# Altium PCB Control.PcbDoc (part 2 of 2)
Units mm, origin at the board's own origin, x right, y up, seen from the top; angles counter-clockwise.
Board outline 30.5 x 82 mm, 2 copper layers (Top Layer, Bottom Layer), stack 1.071 mm thick; 79 components, 65 nets, 365 pads, 467 vias.
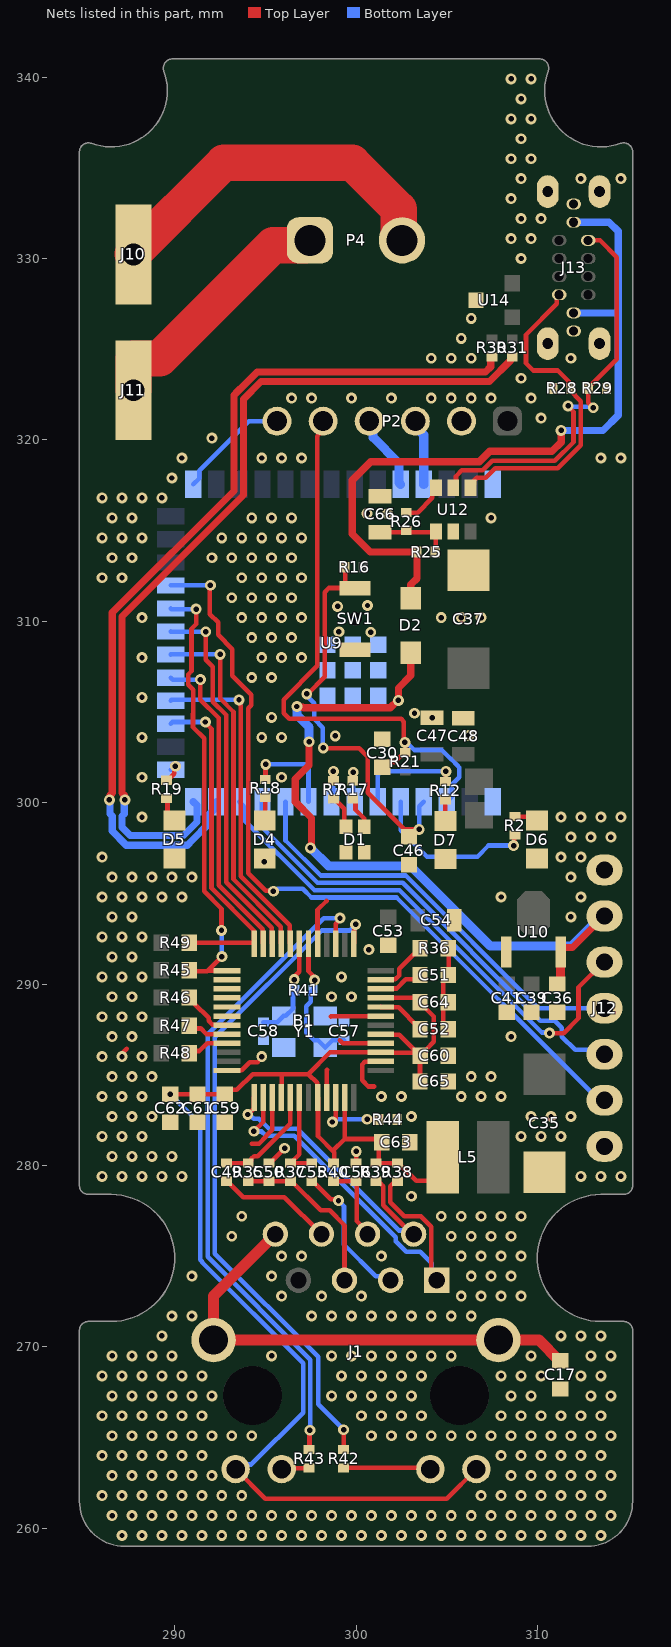
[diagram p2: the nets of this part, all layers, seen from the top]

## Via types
v1: diameter 0.6, hole 0.3, Top Layer to Bottom Layer, tented both sides, 467 vias

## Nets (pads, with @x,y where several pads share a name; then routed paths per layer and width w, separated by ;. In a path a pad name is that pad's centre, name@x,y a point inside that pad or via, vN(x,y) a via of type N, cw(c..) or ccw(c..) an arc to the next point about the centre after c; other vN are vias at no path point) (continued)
G: B1.3 B1.9 B1.14 B1.16 B1.19 B1.29 B1.38 B1.39 B1.40 B1.41 B1.42 B1.48 C17.1 C30.1 C35.2 C36.1 C37.2 C39.1 C41.1 C46.1 C47.1 C48.1 C50.1 C51.2 C52.2 C53.1 C54.1 C56.1 C57.1 C58.1 C59.1 C60.1 C61.1 C62.1 C63.1 C64.1 C65.1 C66.1 D1.3 D1.4 D4.2 D5.2 D6.2 D7.2 J12.1 J12.7 J13.A1/B12 J13.A12/B1 J13.MNT1 J13.MNT2 J13.MNT3 J13.MNT4 P2.2 R28.2 R29.2 R36.2 R44.1 SW1.2 U9.1 U9.40 U9.41 U9.42 U9.43 U9.44 U9.45 U9.46 U9.47 U9.48 U9.49 U10.1 U12.2 U14.3 Y1.2 Y1.4 | length 24.6
  Top Layer w0.254: v1@287.02,286.106 287.35,286.436 ; B1.48@292.738,285.235 292.761,285.258 293.693,285.258 294.134,285.699 294.589,285.699 ; 294.257,281.204 294.649,281.204 295.048,281.603 295.048,281.637 295.377,281.965 B1.3@295.377,283.745 ; C50.1@295.199,280.129 295.249,280.129 296.062,280.942 v1(296.062,280.949) ; B1.29@297.879,292.223 297.879,294.086 298.374,294.581 ; B1.9@298.379,283.747 298.379,285.247 298.399,285.267 ; 298.602,288.214 298.624,288.235 B1.19@301.367,288.235 ; 299.11,286.893 299.268,286.735 B1.16@301.367,286.735 ; C56.1@299.999,280.129 300.006,280.135 300.006,280.77 v1(300.012,280.776) ; 300.99,284.353 300.685,284.353 300.34,284.698 300.34,285.563 300.489,285.712 301.344,285.712 B1.14@301.367,285.735 ; C52.2@304.838,287.452 304.991,287.604 304.82,287.775 304.82,288.729 305.092,289.001 304.82,289.274 304.82,290.227 305.118,290.525 305.118,291.65 305.074,291.694 305.067,291.694 305.067,291.948 R36.2@305.092,291.973
  other v1: 287.1,259.6 288.2,259.6 289.3,259.6 290.4,259.6 291.5,259.6 292.6,259.6 293.7,259.6 294.8,259.6 295.9,259.6 297,259.6 298.1,259.6 299.2,259.6 300.3,259.6 301.4,259.6 302.5,259.6 303.6,259.6 304.7,259.6 305.8,259.6 306.9,259.6 308,259.6 309.1,259.6 310.2,259.6 311.3,259.6 312.4,259.6 313.5,259.6 286.55,260.7 287.65,260.7 288.75,260.7 289.85,260.7 290.95,260.7 292.05,260.7 293.15,260.7 294.25,260.7 295.35,260.7 296.45,260.7 297.55,260.7 298.65,260.7 299.75,260.7 300.85,260.7 301.95,260.7 303.05,260.7 304.15,260.7 305.25,260.7 306.35,260.7 307.45,260.7 308.55,260.7 309.65,260.7 310.75,260.7 311.85,260.7 312.95,260.7 314.05,260.7 286,261.8 287.1,261.8 288.2,261.8 289.3,261.8 290.4,261.8 291.5,261.8 292.6,261.8 293.7,261.8 306.9,261.8 308,261.8 309.1,261.8 310.2,261.8 311.3,261.8 312.4,261.8 313.5,261.8 286.55,262.9 287.65,262.9 288.75,262.9 289.85,262.9 290.95,262.9 292.05,262.9 308.55,262.9 309.65,262.9 310.75,262.9 311.85,262.9 312.95,262.9 314.05,262.9 286,264 287.1,264 288.2,264 289.3,264 290.4,264 291.5,264 308,264 309.1,264 310.2,264 311.3,264 312.4,264 313.5,264 286.55,265.1 287.65,265.1 288.75,265.1 289.85,265.1 290.95,265.1 292.05,265.1 293.15,265.1 294.25,265.1 300.85,265.1 301.95,265.1 303.05,265.1 304.15,265.1 305.25,265.1 306.35,265.1 307.45,265.1 308.55,265.1 309.65,265.1 310.75,265.1 311.85,265.1 312.95,265.1 314.05,265.1 286,266.2 287.1,266.2 288.2,266.2 289.3,266.2 290.4,266.2 291.5,266.2 300.3,266.2 301.4,266.2 302.5,266.2 303.6,266.2 308,266.2 309.1,266.2 310.2,266.2 311.3,266.2 312.4,266.2 313.5,266.2 286.55,267.3 287.65,267.3 288.75,267.3 289.85,267.3 290.95,267.3 292.05,267.3 298.65,267.3 299.75,267.3 300.85,267.3 301.95,267.3 303.05,267.3 308.55,267.3 309.65,267.3 312.95,267.3 314.05,267.3 286,268.4 287.1,268.4 288.2,268.4 289.3,268.4 290.4,268.4 291.5,268.4 299.2,268.4 300.3,268.4 301.4,268.4 302.5,268.4 303.6,268.4 308,268.4 309.1,268.4 310.2,268.4 312.4,268.4 313.5,268.4 286.55,269.5 287.65,269.5 288.75,269.5 289.85,269.5 295.35,269.5 298.65,269.5 299.75,269.5 300.85,269.5 301.95,269.5 303.05,269.5 304.15,269.5 305.25,269.5 309.65,269.5 312.95,269.5 314.05,269.5 289.3,270.6 311.3,270.6 312.4,270.6 313.5,270.6 289.85,271.7 290.95,271.7 297.55,271.7 298.65,271.7 299.75,271.7 300.85,271.7 301.95,271.7 303.05,271.7 304.15,271.7 305.25,271.7 306.35,271.7 295.9,272.8 298.1,272.8 300.3,272.8 305.8,272.8 306.9,272.8 308,272.8 309.1,272.8 290.95,273.9 295.35,273.9 306.35,273.9 307.45,273.9 308.55,273.9 295.9,275 297,275 301.4,275 305.8,275 306.9,275 308,275 309.1,275 293.15,276.1 305.25,276.1 306.35,276.1 307.45,276.1 308.55,276.1 293.7,277.2 304.7,277.2 305.8,277.2 306.9,277.2 308,277.2 309.1,277.2 303.05,278.3 286,279.4 287.1,279.4 288.2,279.4 289.3,279.4 290.4,279.4 312.4,279.4 313.5,279.4 314.6,279.4 286.55,280.5 287.65,280.5 288.75,280.5 289.85,280.5 286,281.6 287.1,281.6 288.2,281.6 309.1,281.6 310.2,281.6 311.3,281.6 286.55,282.7 287.65,282.7 288.75,282.7 303.05,282.7 309.65,282.7 310.75,282.7 311.85,282.7 286,283.8 287.1,283.8 288.2,283.8 301.4,283.8 302.5,283.8 305.8,283.8 306.9,283.8 308,283.8 286.55,284.9 287.65,284.9 288.75,284.9 306.35,284.9 307.45,284.9 286,286 287.1,286 288.2,286 294.8,286 286.55,287.1 287.65,287.1 308.55,287.1 286,288.2 287.1,288.2 288.2,288.2 286.55,289.3 287.65,289.3 298.65,289.3 299.75,289.3 286,290.4 287.1,290.4 288.2,290.4 299.2,290.4 286.55,291.5 287.65,291.5 300.711,291.897 286,292.6 287.1,292.6 288.2,292.6 286.55,293.7 287.65,293.7 311.85,293.7 286,294.8 287.1,294.8 288.2,294.8 289.3,294.8 290.4,294.8 308,294.8 312.4,294.8 286.55,295.9 287.65,295.9 288.75,295.9 289.85,295.9 290.95,295.9 311.85,295.9 294.945,296.748 286,297 311.3,297 312.4,297 311.85,298.1 312.95,298.1 314.05,298.1 288.2,299.2 311.3,299.2 312.4,299.2 313.5,299.2 314.6,299.2 288.2,301.4 295.9,301.4 288.2,303.6 294.8,303.6 295.9,303.6 298.856,303.682 306.222,303.708 304.191,304.682 295.35,304.7 303.225,304.927 288.2,305.8 294.25,306.9 295.35,306.9 288.2,308 294.8,308 295.9,308 297,308 294.25,309.1 295.35,309.1 296.45,309.1 300.812,309.397 299.06,309.423 288.2,310.2 293.7,310.2 294.8,310.2 295.9,310.2 297,310.2 304.7,310.2 305.8,310.2 306.9,310.2 298.983,310.82 300.634,310.871 293.15,311.3 294.25,311.3 295.35,311.3 296.45,311.3 286,312.4 287.1,312.4 293.7,312.4 294.8,312.4 295.9,312.4 297,312.4 286.55,313.5 287.65,313.5 292.05,313.5 293.15,313.5 294.25,313.5 295.35,313.5 296.45,313.5 286,314.6 287.1,314.6 288.2,314.6 292.6,314.6 293.7,314.6 294.8,314.6 295.9,314.6 297,314.6 286.55,315.7 287.65,315.7 294.25,315.7 295.35,315.7 296.45,315.7 307.45,315.7 301.727,315.925 300.609,315.951 286,316.8 287.1,316.8 288.2,316.8 289.3,316.8 289.85,317.9 290.4,319 294.8,319 295.9,319 297,319 313.5,319 314.6,319 292.05,320.1 310.2,321.2 296.45,322.3 297.55,322.3 299.75,322.3 301.95,322.3 304.15,322.3 305.25,322.3 306.35,322.3 307.45,322.3 309.65,322.3 309.1,323.4 304.15,324.5 305.25,324.5 306.35,324.5 311.85,324.5 305.8,325.6 306.35,326.7 309.1,330 308.55,331.1 309.65,331.1 309.1,332.2 310.2,332.2 308.55,333.3 309.1,334.4 312.4,334.4 314.6,334.4 308.55,335.5 309.65,335.5 309.1,336.6 308.55,337.7 309.65,337.7 309.1,338.8 308.55,339.9 309.65,339.9
GND_PE: C17.2 J1.8 J1.13 J1.14 | length 26.8
  Top Layer w0.6: J1.8@295.555,276.215 292.15,272.81 J1.14@292.15,270.375 J1.13@307.85,270.375 310.079,270.375 311.227,269.228 C17.2@311.252,269.228
NetB1_4: B1.4 B1.8 B1.11 B1.15 B1.17 B1.21 C59.2 C60.2 C61.2 C62.2 C63.2 C64.2 C65.2 J1.9 J1.12 L5.2 R38.2 R39.2 R40.1 | length 83
  Top Layer w0.254: v1(289.763,283.934) C61.2@291.262,283.934 C59.2@292.76,283.934 292.991,284.165 293.436,284.165 294.31,285.039 295.899,285.039 ; J1.12@293.36,263.265 295.006,261.619 304.994,261.619 J1.9@306.64,263.265 ; B1.4@295.879,283.747 295.902,283.77 295.902,284.478 295.904,284.48 295.904,285.033 295.899,285.039 ; 298.724,280.802 299.379,281.457 ; R40.1@298.755,280.129 298.811,280.184 298.811,280.716 297.902,281.624 297.902,283.724 297.856,283.77 297.856,284.549 297.367,285.039 ; B1.11@299.379,283.747 299.379,281.457 ; B1.17@301.367,287.235 301.39,287.212 302.385,287.212 303.219,286.378 303.244,286.378 303.307,286.315 303.307,286.29 C60.2@303.542,286.055 ; B1.21@301.367,289.235 301.387,289.255 303.274,289.255 C64.2@303.528,289.001 303.528,288.976 304.292,288.212 304.292,286.811 303.858,286.378 303.84,286.378 303.542,286.08 C60.2@303.542,286.062 ; C60.2@303.23,286.212 301.39,286.212 B1.15@301.367,286.235 298.563,286.235 297.367,285.039 ; C65.2@303.528,284.632 C60.2@303.528,286.04 ; L5.2@304.775,280.441 304.775,279.922 304.002,279.149 303.315,279.149 302.335,280.129 R38.2@302.285,280.129 R39.2@301.092,280.129 301.121,280.129 301.244,280.252 301.244,281.115 C63.2@301.409,281.28 301.231,281.457 299.379,281.457 ; 295.899,285.039 297.367,285.039
  Bottom Layer w0.254: v1(289.763,283.934) 291.412,282.286 291.412,274.792 291.516,274.688 291.516,274.65 297.081,269.085 297.081,266.372 294.225,263.517 293.612,263.517 J1.12@293.36,263.265
NetB1_10: B1.10 R44.2 | length 4.1
  Top Layer w0.254: v1(298.698,282.397) 298.755,282.454 298.755,282.473 298.879,282.598 B1.10@298.879,283.747 ; v1(300.609,282.55) 300.622,282.537 301.239,282.537 R44.2@301.252,282.524
  Bottom Layer w0.254: v1(298.698,282.397) 298.792,282.397 298.944,282.55 v1(300.609,282.55)
NetB1_20: B1.20 C52.1 | length 2.6
  Top Layer w0.254: B1.20@301.367,288.735 301.39,288.712 302.358,288.712 303.441,287.629 C52.1@303.441,287.604
NetB1_22: B1.22 C51.1 | length 2.5
  Top Layer w0.254: B1.22@301.367,289.735 301.39,289.758 302.241,289.758 302.747,290.264 303.307,290.264 C51.1@303.542,290.5
NetB1_23: B1.23 R36.1 | length 3.1
  Top Layer w0.254: B1.23@301.367,290.235 301.39,290.258 302.169,290.258 302.382,290.47 302.382,290.85 303.182,291.65 303.23,291.65 303.528,291.948 R36.1@303.528,291.971
NetB1_25: B1.25 R42.2 | length 37.1
  Top Layer w0.254: R42.2@299.314,264.33 v1(299.314,265.43) ; B1.25@299.879,292.223 299.902,292.246 299.902,293.117 299.978,293.192 v1(299.978,293.286)
  Bottom Layer w0.254: v1(299.314,265.43) 297.917,266.827 297.917,269.443 292.22,275.14 292.22,287.062 298.11,292.952 299.644,292.952 v1(299.978,293.286)
NetB1_27: B1.27 R43.2 | length 36.7
  Top Layer w0.254: R43.2@297.409,264.33 297.434,264.355 297.434,265.379 v1(297.459,265.405) ; B1.27@298.879,292.223 298.879,293.325 299.118,293.563 v1(299.118,293.633)
  Bottom Layer w0.254: v1(297.459,265.405) 297.485,265.43 297.485,269.291 291.816,274.96 291.816,287.229 298.22,293.633 v1(299.118,293.633)
NetB1_30: B1.30 C57.2 R41.2 Y1.1 | length 7.8
  Top Layer w0.254: B1.30@297.379,292.223 297.379,290.702 297.713,290.368 v1(297.713,290.22)
  Bottom Layer w0.254: v1(297.713,290.22) 297.671,290.178 297.671,289.704 297.506,289.539 297.506,289.019 297.256,288.769 297.256,287.325 297.682,286.899 297.907,286.899 Y1.1@298.305,286.501 298.703,286.899 299.337,286.899 C57.2@299.339,286.901
NetB1_31: B1.31 C58.2 R41.1 Y1.3 | length 7.1
  Top Layer w0.254: v1(296.596,290.246) 296.596,290.394 296.879,290.677 B1.31@296.879,292.223
  Bottom Layer w0.254: C58.2@294.894,287.901 295.656,287.901 295.664,287.893 296.021,288.251 Y1.3@296.13,288.251 ; R41.1@296.596,289.662 v1(296.596,290.246) ; R41.1@296.629,289.662 296.528,289.56 Y1.3@296.528,288.649 ; Y1.3@296.13,288.251 Y1.3@296.005,288.251 Y1.3@296.13,288.251 ; Y1.3@296.13,288.251 Y1.3@296.528,288.649 ; Y1.3@296.13,288.251 Y1.3@296.528,288.649 ; Y1.3@296.13,288.251 Y1.3@296.528,288.649
NetB1_32: B1.32 U9.18 | length 18.4
  Top Layer w0.254: v1(293.548,305.664) 293.614,305.597 293.614,305.38 293.652,305.342 293.652,295.944 296.356,293.239 296.356,292.246 B1.32@296.379,292.223
  Bottom Layer w0.254: U9.18@289.783,305.625 289.822,305.664 v1(293.548,305.664)
NetB1_33: B1.33 U9.20 | length 20.1
  Top Layer w0.254: v1(292.506,308.178) 292.506,305.742 293.248,305.001 293.248,295.777 295.856,293.168 295.856,292.246 B1.33@295.879,292.223
  Bottom Layer w0.254: U9.20@289.783,308.165 289.796,308.178 v1(292.506,308.178)
NetB1_34: B1.34 U9.21 | length 20.7
  Top Layer w0.254: v1(291.719,309.423) 291.719,307.873 292.102,307.49 292.102,305.575 292.844,304.833 292.844,295.609 295.356,293.097 295.356,292.246 B1.34@295.379,292.223
  Bottom Layer w0.254: U9.21@289.783,309.435 289.796,309.423 v1(291.719,309.423)
NetB1_35: B1.35 U9.19 | length 17.7
  Top Layer w0.254: v1(291.421,306.786) 291.421,305.684 292.44,304.666 292.44,295.442 294.856,293.025 294.856,292.246 B1.35@294.879,292.223
  Bottom Layer w0.254: U9.19@289.783,306.895 289.892,306.786 v1(291.421,306.786)
NetB1_36: B1.36 R49.2 U9.17 | length 18.8
  Top Layer w0.254: R49.2@290.818,292.278 B1.36@294.356,292.278 ; v1(291.695,304.448) 291.695,304.403 292.036,304.062 292.036,295.274 294.356,292.954 B1.36@294.356,292.278 ; B1.36@294.379,292.223 294.379,292.255 B1.36@294.356,292.278
  Bottom Layer w0.254: U9.17@289.783,304.355 289.876,304.448 v1(291.695,304.448)
NetB1_37: B1.37 R45.2 U9.22 | length 24.8
  Top Layer w0.254: R45.2@290.818,290.754 290.868,290.703 291.795,290.703 v1(292.608,291.516) ; v1(291.186,310.667) 291.186,309.852 290.932,309.598 290.932,307.259 290.74,307.068 290.74,306.504 291.017,306.227 291.017,304.9 291.014,304.896 291.014,304.166 291.632,303.548 291.632,295.107 292.583,294.156 v1(292.583,292.964) ; 291.795,290.735 B1.37@292.891,290.735
  Bottom Layer w0.254: U9.22@289.783,310.705 289.821,310.667 v1(291.186,310.667) ; v1(292.583,292.964) 292.595,292.951 292.595,291.529 v1(292.608,291.516)
NetB1_43: B1.43 R46.2 | length 2.8
  Top Layer w0.254: R46.2@290.818,289.255 291.116,288.957 291.116,288.893 291.877,288.132 291.877,287.97 292.089,287.758 292.868,287.758 B1.43@292.891,287.735
NetB1_44: B1.44 R47.2 | length 2.3
  Top Layer w0.254: R47.2@290.818,287.706 290.97,287.553 291.44,287.553 291.758,287.235 B1.44@292.891,287.235
NetB1_45: B1.45 R48.2 | length 2.4
  Top Layer w0.254: R48.2@290.818,286.182 290.881,286.118 291.072,286.309 291.363,286.309 291.79,286.735 B1.45@292.891,286.735
NetC30_2: C30.2 P2.5 R21.1 U9.3 | length 32.9
  Top Layer w0.254: P2.5@298.19,321.031 297.932,320.773 297.932,320.273 297.868,320.209 297.868,307.539 296.012,305.682 296.012,304.924 296.314,304.622 302.489,304.622 302.641,304.47 302.641,303.378 v1(302.692,303.327) 302.704,303.314 302.704,302.773 R21.1@302.717,302.76 302.667,302.76 302.147,302.24 301.745,302.24 C30.2@301.447,301.942
  Bottom Layer w0.254: v1(302.692,303.327) 302.785,303.327 303.211,302.901 304.729,302.901 305.222,302.408 305.234,302.408 305.633,302.009 305.633,301.997 305.689,301.941 305.689,301.396 305.288,300.996 305.288,300.335 U9.3@305.003,300.05
NetC46_2: C46.2 R16.1 SW1.1 U9.4 | length 22.3
  Top Layer w0.254: v1(297.286,305.994) 297.33,305.994 298.272,306.936 298.272,311.607 298.499,311.834 SW1.1@299.259,311.834 ; v1(298.196,303.022) 298.217,303.001 300.17,303.001 300.655,302.517 300.655,300.538 302.666,298.526 v1(303.479,298.526) ; R16.1@299.398,312.979 299.398,311.973 SW1.1@299.259,311.834 ; SW1.1@299.949,311.834 SW1.1@299.259,311.834
  Bottom Layer w0.254: v1(297.286,305.994) 297.286,305.9 297.696,305.49 297.696,304.619 298.175,304.14 298.175,303.043 v1(298.196,303.022) ; v1(303.479,298.526) 303.479,299.796 U9.4@303.733,300.05
NetC50_2: C50.2 J1.5 R35.2 R37.1 | length 9.3
  Top Layer w0.254: R35.2@294.056,279.129 C50.2@295.199,279.129 296.22,279.129 296.443,279.129 298.051,277.52 298.552,277.52 299.365,276.707 J1.5@299.365,273.675
NetC56_2: C56.2 J1.4 R40.2 | length 4.5
  Top Layer w0.254: R40.2@298.755,279.129 300.049,279.129 300.049,276.937 300.635,276.351 J1.4@300.635,276.215
NetC66_2: C66.2 R25.2 R26.1 U12.1 | length 4.3
  Top Layer w0.254: C66.2@301.32,314.9 304.355,314.9 U12.1@304.409,314.954 304.388,314.934 304.388,313.837 R25.2@304.368,313.817
NetD1_1: D1.1 R7.1 | length 1.9
  Top Layer w0.254: R7.1@298.755,300.211 298.805,300.211 299.353,299.662 299.353,298.763 D1.1@299.449,298.667
NetD1_2: D1.2 R17.1 | length 1.8
  Top Layer w0.254: R17.1@299.822,300.211 299.851,300.211 299.974,300.088 299.974,299.601 300.449,299.126 D1.2@300.449,298.667
NetD4_1: D4.1 R18.1 | length 1.3
  Top Layer w0.254: D4.1@294.97,299.017 294.996,299.043 R18.1@294.996,300.287
NetD5_1: D5.1 R19.1 | length 1.4
  Top Layer w0.254: R19.1@289.56,300.236 289.607,300.189 289.607,299.402 D5.1@289.992,299.017
NetD6_1: D6.1 R2.1 | length 1.4
  Top Layer w0.254: R2.1@308.762,299.229 309.516,299.229 309.643,299.356 D6.1@309.982,299.017
NetD7_1: D7.1 R12.1 | length 1.2
  Top Layer w0.254: D7.1@304.927,298.992 R12.1@304.927,300.16
NetJ1_10: J1.10 R42.1 | length 4.8
  Top Layer w0.254: R42.1@299.314,263.33 304.035,263.33 J1.10@304.1,263.265
NetJ1_11: J1.11 R43.1 | length 1.5
  Top Layer w0.254: J1.11@295.9,263.265 295.932,263.297 297.376,263.297 R43.1@297.409,263.33
NetJ10_1: J10.1 P4.2 | length 19.6
  Top Layer w2: J10.1@287.68,330.251 292.71,335.28 299.796,335.28 302.358,332.718 302.358,331.182 P4.2@302.54,331
NetJ11_1: J11.1 P4.1 | length 14.2
  Top Layer w2: J11.1@287.731,322.733 287.731,324.483 289.177,324.483 295.419,330.725 297.185,330.725 P4.1@297.46,331
NetJ12_3: J12.3 U9.12 | length 28.4
  Top Layer w0.254: v1(310.667,287.299) 311.455,287.299 312.268,288.112 312.268,289.814 J12.3@313.665,291.211
  Bottom Layer w0.254: U9.12@293.573,300.05 293.819,299.804 293.819,299.068 297.711,295.176 302.399,295.176 310.244,287.331 310.636,287.331 v1(310.667,287.299)
NetJ12_4: J12.4 U9.10 | length 23.5
  Bottom Layer w0.254: U9.10@296.113,300.05 296.113,297.917 298.046,295.984 302.734,295.984 310.047,288.671 J12.4@313.665,288.671
NetJ12_5: J12.5 U9.11 | length 25.7
  Bottom Layer w0.254: U9.11@294.843,300.05 294.818,300.025 294.818,298.641 297.879,295.58 302.567,295.58 310.166,287.98 310.949,287.98 311.348,287.581 311.348,287.101 312.076,286.373 313.423,286.373 J12.5@313.665,286.131
NetJ12_6: J12.6 U9.23 | length 44
  Top Layer w0.254: v1(291.973,311.988) 291.946,311.961 291.946,310.397 292.4,309.943 292.4,309.248 293.187,308.46 293.187,307.724 293.187,306.987 293.83,306.345 294.229,305.946 294.229,305.382 294.056,305.209 294.056,296.111 295.021,295.146 295.413,295.146 v1(295.444,295.114)
  Bottom Layer w0.254: U9.23@289.796,311.988 v1(291.973,311.988) ; v1(295.444,295.114) 295.538,295.114 295.684,295.261 297.055,295.261 297.544,294.772 302.232,294.772 313.413,283.591 J12.6@313.665,283.591
NetJ13_A5: J13.A5 R28.1 U12.4 | length 18.3
  Top Layer w0.254: U12.4@306.309,317.354 306.507,317.552 306.507,317.771 306.656,317.92 307.16,317.92 307.68,318.44 311.125,318.44 312.395,319.71 312.395,322.14 311.777,322.758 R28.1@311.853,322.834 311.73,322.957 311.73,323.219 311.125,323.825 309.781,323.825 309.372,324.233 309.372,325.806 311.07,327.504 311.07,327.87 J13.A5@311.2,328
NetJ13_B5: J13.B5 R29.1 U12.5 | length 22.5
  Top Layer w0.254: U12.5@305.359,317.354 305.513,317.508 305.513,318.005 305.833,318.324 306.993,318.324 307.512,318.844 310.957,318.844 311.991,319.877 311.991,321.557 311.693,321.854 v1(311.693,321.879) ; J13.B5@312.8,331 313.449,331 314.376,330.073 314.376,324.451 312.809,322.884 312.809,322.038 v1(313.076,321.772)
  Bottom Layer w0.254: v1(311.693,321.879) 311.747,321.825 313.022,321.825 v1(313.076,321.772)
NetP2_3: P2.3 U9.37 | length 3.7
  Bottom Layer w0.5: P2.3@303.27,321.031 303.27,320.733 303.733,320.27 U9.37@303.733,317.55
NetP2_4: P2.4 U9.36 | length 4.2
  Bottom Layer w0.5: P2.4@300.73,321.031 300.94,320.82 300.94,320.138 302.365,318.713 302.365,317.648 U9.36@302.463,317.55
NetP2_6: P2.6 U9.27 | length 6.3
  Bottom Layer w0.254: U9.27@291.033,317.55 291.356,317.873 291.356,318.291 294.096,321.031 P2.6@295.65,321.031
NetR2_2: R2.2 U9.5 | length 9.3
  Top Layer w0.254: v1(308.686,297.637) 308.724,297.675 308.724,298.191 R2.2@308.762,298.229
  Bottom Layer w0.254: U9.5@302.463,300.05 302.463,298.475 303.911,297.028 306.695,297.028 307.305,297.637 v1(308.686,297.637)
NetR7_2: R7.2 U9.8 | length 2.2
  Top Layer w0.254: R7.2@298.755,301.211 v1(298.755,301.727)
  Bottom Layer w0.254: U9.8@298.653,300.05 298.755,300.152 v1(298.755,301.727)
NetR12_2: R12.2 U9.6 | length 5.9
  Top Layer w0.254: R12.2@304.927,301.16 304.94,301.172 304.94,301.714 v1(304.952,301.727)
  Bottom Layer w0.254: U9.6@301.193,300.05 301.193,301.523 301.396,301.727 v1(304.952,301.727)
NetR17_2: R17.2 U9.7 | length 2.1
  Top Layer w0.254: R17.2@299.822,301.211 299.834,301.223 299.834,301.663 v1(299.847,301.676)
  Bottom Layer w0.254: v1(299.847,301.676) 299.847,300.126 U9.7@299.923,300.05
NetR18_2: R18.2 U9.9 | length 5.3
  Top Layer w0.254: R18.2@294.996,301.287 295.008,301.299 295.008,302.095 v1(295.021,302.108)
  Bottom Layer w0.254: v1(295.021,302.108) 297.383,302.108 U9.9@297.383,300.05
NetR19_2: R19.2 U9.15 | length 1.3
  Top Layer w0.254: R19.2@289.56,301.236 289.61,301.236 289.976,301.602 289.976,301.94 v1(290.043,302.006)
  Bottom Layer w0.254: U9.15@289.783,301.815 289.852,301.815 v1(290.043,302.006)
NetR26_2: R26.2 U12.6 | length 2.4
  Top Layer w0.254: R26.2@302.768,315.993 303.395,315.993 304.211,316.809 304.211,317.156 U12.6@304.409,317.354
RX_N: B1.5 C49.2 R35.1 | length 6
  Top Layer w0.25: C49.2@292.862,280.129 R35.1@294.106,280.129 ; R35.1@294.056,280.129 R35.1@294.106,280.129 ; B1.5@296.379,283.747 296.379,282.308 294.586,280.515 294.377,280.515 294.231,280.368 294.231,280.254 R35.1@294.106,280.129
RX_P: B1.6 C55.2 R37.2 | length 5
  Top Layer w0.25: B1.6@296.883,283.747 296.883,280.619 296.568,280.304 296.568,280.254 296.443,280.129 R37.2@296.393,280.129 296.568,280.129 C55.2@297.561,280.129
RXN_N: C49.1 J1.6 | length 6.4
  Top Layer w0.254: C49.1@292.862,279.129 292.912,279.129 293.784,278.257 296.053,278.257 298.086,276.224 J1.6@298.095,276.224
RXN_P: C55.1 J1.3 | length 7.8
  Top Layer w0.254: C55.1@297.561,279.129 297.611,279.129 298.611,278.129 298.968,278.129 v1(299.034,278.063)
  Bottom Layer w0.254: v1(299.034,278.063) 299.034,278.046 299.339,277.741 299.339,275.641 301.086,273.894 301.686,273.894 J1.3@301.905,273.675
TX_N: B1.1 J1.2 R39.1 | length 16.9
  Top Layer w0.257: v1(294.029,282.81) 294.379,283.16 B1.1@294.379,283.747 ; R39.1@301.092,279.129 301.213,279.007 301.346,279.007 301.497,278.857 301.497,277.804 J1.2@303.175,276.126
  Bottom Layer w0.257: v1(294.029,282.81) 294.122,282.81 294.364,282.568 294.65,282.568 295.202,282.015 296.761,282.015 302.357,276.418 302.972,276.418 J1.2@303.175,276.215
TX_P: B1.2 J1.1 R38.1 | length 23.4
  Top Layer w0.257: v1(294.367,281.885) 294.879,282.397 B1.2@294.879,283.747 ; R38.1@302.285,279.129 302.164,279.007 302.031,279.007 301.88,278.857 301.88,277.963 302.65,277.193 303.58,277.193 304.153,276.62 304.153,273.967 J1.1@304.445,273.675
  Bottom Layer w0.257: v1(294.367,281.885) 294.383,281.869 294.806,281.869 295.043,281.632 296.602,281.632 302.197,276.037 302.197,275.81 302.77,275.237 303.539,275.237 304.166,274.61 304.166,273.954 J1.1@304.445,273.675
USB_D_N: R30.1 U9.13 | length 49.8
  Top Layer w0.403: v1(286.404,300.152) 286.442,300.19 286.442,300.404 286.567,300.528 286.567,310.48 293.268,317.182 293.268,322.465 293.423,322.62 293.858,323.055 294.237,323.434 294.548,323.745 307.137,323.745 307.428,324.035 307.428,324.52 307.476,324.569 R30.1@307.492,324.569
  Bottom Layer w0.403: v1(286.404,300.152) 286.442,300.114 286.442,299.387 286.567,299.263 286.567,298.434 287.341,297.66 290.706,297.66 291.016,297.97 291.834,298.788 291.834,299.281 292.303,299.75 U9.13@292.303,300.05
USB_D_P: R31.1 U9.14 | length 48.2
  Top Layer w0.403: v1(287.258,300.152) 287.221,300.19 287.221,300.404 287.096,300.528 287.096,310.261 293.798,316.963 293.798,322.246 294.767,323.215 307.356,323.215 308.511,324.37 308.511,324.52 308.56,324.569 R31.1@308.61,324.569
  Bottom Layer w0.403: v1(287.258,300.152) 287.221,300.114 287.221,299.387 287.096,299.263 287.096,298.653 287.56,298.189 290.487,298.189 291.23,298.932 291.23,299.854 U9.14@291.033,300.05
V_BUS: D2.2 J13.A4/B9 J13.B4/A9 R25.1 | length 41.4
  Top Layer w0.4: D2.2@303.022,311.278 303.022,312.03 303.368,312.376 R25.1@303.368,313.817 300.787,313.817 299.796,314.808 299.796,317.781 300.816,318.801 306.795,318.801 307.366,319.372 310.81,319.372 311.31,319.871 v1(311.31,320.523)
  Bottom Layer w0.4: v1(311.31,320.523) 313.614,320.523 314.452,321.36 314.452,331.496 313.947,332 J13.B4/A9@312,332 ; J13.A4/B9@312,327 314.452,327
VCC_2: C36.2 D2.1 J12.2 U10.3 | length 41.5
  Top Layer w0.4: v1(296.738,305.303) 296.776,305.265 297.082,305.265 297.107,305.24 301.884,305.24 302.282,305.638 v1(302.336,305.638) 302.336,306.324 303.022,307.01 D2.1@303.022,308.278 ; v1(297.412,303.362) 297.412,302.057 296.655,301.299 296.655,300.049 297.548,299.156 297.548,297.744 297.522,297.718 297.522,297.547 v1(297.484,297.509) ; U10.3@311.341,292.015 311.929,292.015 J12.2@313.665,293.751
  Top Layer w0.5: C36.2@311.099,290.005 311.103,290.005 311.278,290.18 U10.3@311.278,291.767
  Bottom Layer w0.5: v1(296.738,305.303) 296.757,305.284 296.757,304.813 297.412,304.158 v1(297.412,303.362) ; v1(297.484,297.509) 298.482,296.511 302.999,296.511 307.409,292.1 311.899,292.1 313.55,293.751 J12.2@313.7,293.751
pads on no net: B1.7 B1.12 B1.13 B1.18 B1.24 B1.26 B1.46 B1.47 J1. J1.7 J13.A8 J13.B8 SW1. U9.16 U9.24 U9.25 U9.26 U9.28 U9.29 U9.30 U9.31 U9.32 U9.33 U9.34 U9.35 U9.38 U9.39 U12.3

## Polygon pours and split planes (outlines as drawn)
G on Bottom Layer "G_L02_P002" (solid, pour order 2): 284.707,261.452 284.707,270.852 cw(c285.206,270.852) 285.207,271.352 286.457,271.352 ccw(c286.457,274.852) 286.457,278.352 285.207,278.352 cw(c285.206,278.852) 284.707,278.852 284.707,318.189 288.93,318.189 293.014,324.739 303.632,324.739 308.012,329.12 308.012,340.952 310.081,340.952 cw(c310.081,340.452) 310.549,340.278 ccw(c313.456,339.202) 314.533,336.295 cw(c314.707,335.826) 315.207,335.826 315.207,278.852 cw(c314.707,278.852) 314.707,278.352 313.457,278.352 ccw(c313.457,274.852) 313.457,271.352 314.707,271.352 cw(c314.707,270.852) 315.207,270.852 315.207,261.452 cw(c312.707,261.452) 312.707,258.952 287.207,258.952 cw(c287.207,261.452)
G on Top Layer "G_L01_P003" (solid, pour order 3): 284.687,261.514 284.687,270.914 cw(c285.187,270.914) 285.187,271.414 286.437,271.414 ccw(c286.437,274.914) 286.437,278.414 285.187,278.414 cw(c285.187,278.914) 284.687,278.914 284.687,318.252 289.022,318.252 293.027,324.764 302.362,324.764 307.899,330.302 307.899,341.014 310.061,341.014 cw(c310.061,340.515) 310.53,340.341 ccw(c313.437,339.264) 314.513,336.357 cw(c314.687,335.889) 315.187,335.888 315.187,278.914 cw(c314.687,278.914) 314.687,278.414 313.437,278.414 ccw(c313.437,274.914) 313.437,271.414 314.687,271.414 cw(c314.687,270.915) 315.187,270.914 315.187,261.514 cw(c312.687,261.514) 312.687,259.014 287.187,259.014 cw(c287.187,261.514)

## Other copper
Top Layer:
  pour cut-out: 308.254,299.949 308.254,317.83 315.239,317.83 315.239,299.949
Bottom Layer:
  pour cut-out: 308.254,317.83 315.218,317.83 315.218,299.822 308.254,299.822

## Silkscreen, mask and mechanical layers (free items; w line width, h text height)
Top Overlay:
  drawing of 256 lines, arcs and shapes, not listed
  text "RX" at 299.491,322.885 h1.1 r90
  text "EN" at 297.764,322.859 h1.1 r90
  text "TX" at 301.32,322.859 h1.1 r90
  text "BOOT" at 296.088,322.809 h1.1 r90
  text "GND" at 302.971,322.809 h1.1 r90
  text "+3.3V" at 305.232,322.758 h1.1 r90
  text "1" at 314.541,298.336 h1.02
  text "7" at 310.717,281.126 h1.02 r270
Bottom Overlay:
  lines w0.013: 285.25,271.4 ccw(c285.25,270.9) 284.75,270.9 284.75,261.5 ccw(c287.25,261.5) 287.25,259 292,259 ; 285.25,278.4 cw(c285.25,278.9) 284.75,278.9 284.75,335.874 cw(c285.25,335.874) 285.424,336.343 ccw(c286.5,339.25) 289.407,340.326 cw(c289.876,340.5) 289.876,341 310.124,341 cw(c310.124,340.5) 310.593,340.326 ccw(c313.5,339.25) 314.576,336.343 cw(c314.75,335.874) 315.25,335.874 315.25,278.9 cw(c314.75,278.9) 314.75,278.4 313.5,278.4 ccw(c313.5,274.9) 313.5,271.4 314.75,271.4 cw(c314.75,270.9) 315.25,270.9 315.25,261.5 cw(c312.75,261.5) 312.75,259 308,259 ; 292,277.8 292,256.5 308,256.5 308,277.8 ; 293.92,338.54 306.08,338.54 ; 293.92,339.827 306.08,339.827 ; 293.92,341 293.92,329 306.08,329 306.08,341 ; 296.413,341 296.96,339.827 ; 297.96,339.827 298.507,341 ; 301.493,341 302.04,339.827 ; 303.04,339.827 303.587,341
  lines w0.1: 298.069,305.511 301.623,305.511 301.623,309.04 298.069,309.04 298.069,305.511
Mechanical 1:
  lines w0.013: 285.25,271.4 ccw(c285.25,270.9) 284.75,270.9 284.75,261.5 ccw(c287.25,261.5) 287.25,259 312.75,259 ccw(c312.75,261.5) 315.25,261.5 315.25,270.9 ccw(c314.75,270.9) 314.75,271.4 313.5,271.4 cw(c313.5,274.9) 313.5,278.4 314.75,278.4 ccw(c314.75,278.9) 315.25,278.9 315.25,335.874 ccw(c314.75,335.874) 314.576,336.343 cw(c313.5,339.25) 310.593,340.326 ccw(c310.124,340.5) 310.124,341 289.876,341 ccw(c289.876,340.5) 289.407,340.326 cw(c286.5,339.25) 285.424,336.343 ccw(c285.25,335.874) 284.75,335.874 284.75,278.9 ccw(c285.25,278.9) 285.25,278.4
  lines w0.1: 285.717,319.28 285.717,319.303 288.73,319.303 288.73,319.28 285.717,319.28 ; 289.129,319.203 289.306,319.203 289.306,322.986 289.129,322.986 289.129,319.203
